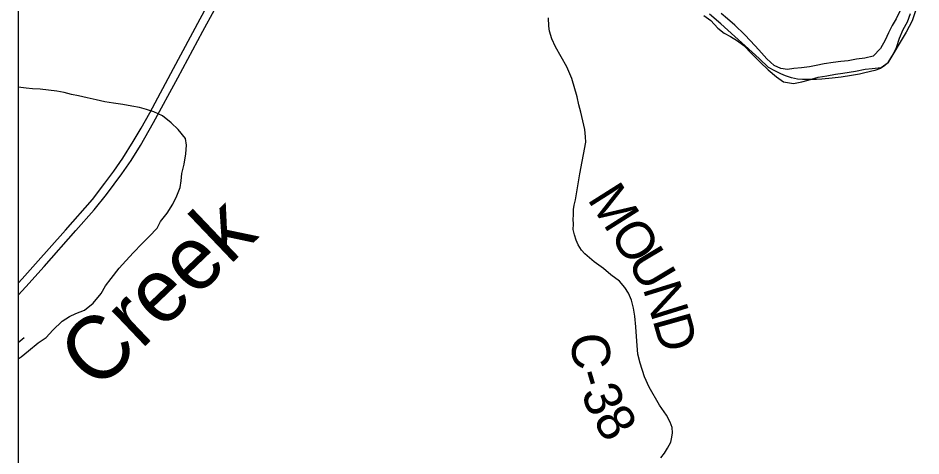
# Model space of a CAD drawing. Extents: x 0 to 34, y 0 to 22.
# Drawn here: x 2.1 to 3.455, y 17.141 to 17.798 of the extents above; entities that cross this region are included whole.
import ezdxf

# ---------------------------------------------------------------- set-up
doc = ezdxf.new("R2010")
doc.units = 0
for name, color, linetype in [('GM_X_Corporation', 7, 'Continuous'), ('GM_X_County_Road', 7, 'Continuous'), ('GM_X_County_Road_Text', 7, 'Continuous'), ('GM_X_Major_River', 7, 'Continuous'), ('GM_X_Major_River_Text', 7, 'Continuous'), ('GM_X_State_Route', 7, 'Continuous'), ('GM_X_Township_Road', 7, 'Continuous'), ('SH_Data', 7, 'Continuous')]:
    doc.layers.add(name, color=color, linetype=linetype)

msp = doc.modelspace()

# ---------------------------------------------------------------- linework, layer by layer
at = {"layer": 'GM_X_Corporation'}
msp.add_lwpolyline([(4.1215, 17.0136), (4.1603, 17.6679), (4.1853, 18.0392), (4.1964, 18.2095), (4.2079, 18.3668), (4.2088, 18.3789), (4.2282, 18.6426), (4.2537, 18.9868), (4.2536, 19.0552), (4.2737, 19.3421), (4.2893, 19.6309), (4.3029, 19.8336), (4.3134, 19.9898), (4.3401, 20.3869), (4.364, 20.7926), (4.3772, 20.9), (2.1, 20.9), (2.1, 14.9497)], dxfattribs=at)
at = {"layer": 'GM_X_County_Road'}
msp.add_lwpolyline([(3.0646, 17.1383), (3.0699, 17.1452), (3.0745, 17.1525), (3.0795, 17.1616), (3.0812, 17.1694), (3.0819, 17.1755), (3.0816, 17.1839), (3.0783, 17.1918), (3.0729, 17.2022), (3.0626, 17.2173), (3.0472, 17.244), (3.0398, 17.2599), (3.0333, 17.2801), (3.0298, 17.2937), (3.0283, 17.3134), (3.0269, 17.3349), (3.0254, 17.3508), (3.0235, 17.3628), (3.0203, 17.3747), (3.0159, 17.3852), (3.0106, 17.3935), (3.0023, 17.4029), (2.9894, 17.4124), (2.9785, 17.4223), (2.9647, 17.432), (2.9506, 17.4439), (2.9456, 17.4496), (2.9407, 17.4575), (2.9374, 17.4645), (2.9348, 17.4725), (2.9332, 17.4808), (2.9334, 17.4885), (2.9332, 17.4962), (2.9334, 17.502), (2.9336, 17.5104), (2.9345, 17.517), (2.9363, 17.5251), (2.9432, 17.5641), (2.952, 17.6114), (2.9514, 17.6195), (2.9503, 17.6306), (2.9476, 17.6436), (2.9445, 17.6568), (2.9416, 17.6674), (2.939, 17.6797), (2.931, 17.7072), (2.9236, 17.7246), (2.9066, 17.7546), (2.9012, 17.7666), (2.8977, 17.7778), (2.8963, 17.7854), (2.8962, 17.7978)], dxfattribs=at)
at = {"layer": 'GM_X_Major_River'}
msp.add_line((2.1091, 17.3182), (2.1, 17.3108), dxfattribs=at)
for points in [[(3.1291, 17.8017), (3.1393, 17.7941), (3.15, 17.7823), (3.1594, 17.7751), (3.1693, 17.7701), (3.1796, 17.7633), (3.189, 17.7565), (3.2012, 17.7439), (3.2137, 17.7318), (3.2258, 17.72), (3.238, 17.7094), (3.2486, 17.7022), (3.2634, 17.6995), (3.2759, 17.7021), (3.2854, 17.7044), (3.3006, 17.7089), (3.3135, 17.7112), (3.3265, 17.7135), (3.3375, 17.715), (3.3473, 17.7165), (3.3568, 17.718), (3.3709, 17.721), (3.3815, 17.7222), (3.3952, 17.7237), (3.4055, 17.7309), (3.4138, 17.7438), (3.418, 17.7536), (3.4226, 17.7677), (3.4279, 17.7806), (3.4348, 17.792), (3.4393, 17.8045)], [(3.4234, 17.809), (3.4177, 17.7965), (3.4116, 17.7863), (3.4059, 17.7753), (3.4009, 17.7647), (3.3941, 17.7521), (3.3831, 17.7404), (3.3705, 17.7374), (3.358, 17.7358), (3.3458, 17.7336), (3.3348, 17.7325), (3.3231, 17.7309), (3.3094, 17.7291), (3.2976, 17.7268), (3.2877, 17.7245), (3.2756, 17.723), (3.2642, 17.7219), (3.2547, 17.7207), (3.2444, 17.7223), (3.2346, 17.7268), (3.2236, 17.7367), (3.2118, 17.75), (3.1993, 17.7637), (3.1902, 17.7732), (3.1754, 17.7872), (3.1648, 17.7967), (3.1549, 17.8047)], [(2.1, 17.2865), (2.1049, 17.2897), (2.1159, 17.2988), (2.1303, 17.3106), (2.1421, 17.3189), (2.1524, 17.3299), (2.1664, 17.3432), (2.1774, 17.35), (2.1869, 17.3546), (2.1999, 17.3595), (2.2128, 17.3701), (2.2246, 17.3849), (2.2314, 17.3959), (2.2398, 17.4073), (2.2516, 17.4225), (2.2618, 17.4338), (2.2732, 17.4463), (2.2858, 17.4592), (2.2968, 17.4699), (2.3086, 17.4828), (2.3139, 17.4926), (2.3238, 17.5051), (2.3322, 17.5184), (2.3382, 17.5313), (2.3432, 17.5438), (2.3447, 17.5537), (2.3459, 17.5647), (2.3493, 17.5787), (2.352, 17.5943), (2.3527, 17.6072), (2.3512, 17.6171), (2.3402, 17.6304), (2.3296, 17.6406), (2.3167, 17.6509), (2.3038, 17.657), (2.2928, 17.6608), (2.2822, 17.6634), (2.2708, 17.6657), (2.2571, 17.668), (2.2431, 17.6703), (2.2302, 17.6722), (2.2173, 17.6749), (2.2036, 17.6779), (2.1907, 17.6809), (2.1801, 17.6832), (2.169, 17.6863), (2.158, 17.6882), (2.1459, 17.6897), (2.1334, 17.6909), (2.1216, 17.6916), (2.1121, 17.6924), (2.1, 17.6941)]]:
    msp.add_lwpolyline(points, dxfattribs=at)
at = {"layer": 'GM_X_State_Route'}
for points in [[(2.1, 17.3999), (2.106, 17.4064), (2.1264, 17.4293), (2.1712, 17.4798), (2.2119, 17.5257), (2.2304, 17.5502), (2.2437, 17.5679), (2.2572, 17.5877), (2.2727, 17.6127), (2.2848, 17.6327), (2.2978, 17.6558), (2.333, 17.7221), (2.3735, 17.7966), (2.421, 17.8843)], [(2.1, 17.3821), (2.1117, 17.3948), (2.1391, 17.4253), (2.1865, 17.479), (2.214, 17.5102), (2.2328, 17.5331), (2.2557, 17.5641), (2.2695, 17.5843), (2.2835, 17.6068), (2.303, 17.6409), (2.3396, 17.7082), (2.3774, 17.7779), (2.4297, 17.8746)]]:
    msp.add_lwpolyline(points, dxfattribs=at)
at = {"layer": 'GM_X_Township_Road'}
msp.add_lwpolyline([(3.4475, 17.8113), (3.4417, 17.7936), (3.4327, 17.7767), (3.405, 17.7304), (3.4001, 17.7259), (3.3941, 17.722), (3.3854, 17.7192), (3.3705, 17.7154), (3.3627, 17.7136), (3.3505, 17.7114), (3.3351, 17.709), (3.3218, 17.7075), (3.3063, 17.7061), (3.2981, 17.7058), (3.2868, 17.7058), (3.2772, 17.7056), (3.2695, 17.7063), (3.2607, 17.7081), (3.2517, 17.711), (3.2445, 17.7139), (3.2354, 17.7185), (3.2262, 17.7238), (3.2123, 17.7368), (3.1547, 17.7891), (3.1376, 17.8037)], dxfattribs=at)
at = {"layer": 'SH_Data'}
msp.add_line((2.1, 20.9), (2.1, 14.1), dxfattribs=at)

# ---------------------------------------------------------------- texts
at = {"layer": 'GM_X_County_Road_Text'}
for s, rotation, p in [('M', 302.3022, (2.9534, 17.5263)), ('O', 302.2977, (2.9864, 17.4742)), ('U', 300.9207, (3.0129, 17.4322)), ('N', 287.2184, (3.0371, 17.3926)), ('D', 285.7983, (3.0518, 17.3452)), ('C', 274.5792, (2.9292, 17.3233)), ('-', 286.505, (2.9353, 17.2641)), ('3', 292.1929, (2.944, 17.2359)), ('8', 301.2445, (2.9616, 17.1948))]:
    msp.add_text(s, height=0.0568, rotation=rotation, dxfattribs=at).set_placement(p)
at = {"layer": 'GM_X_Major_River_Text'}
msp.add_text('Creek', height=0.0947, rotation=43.6532, dxfattribs=at).set_placement((2.2183, 17.2366))

doc.saveas('drawing.dxf')
